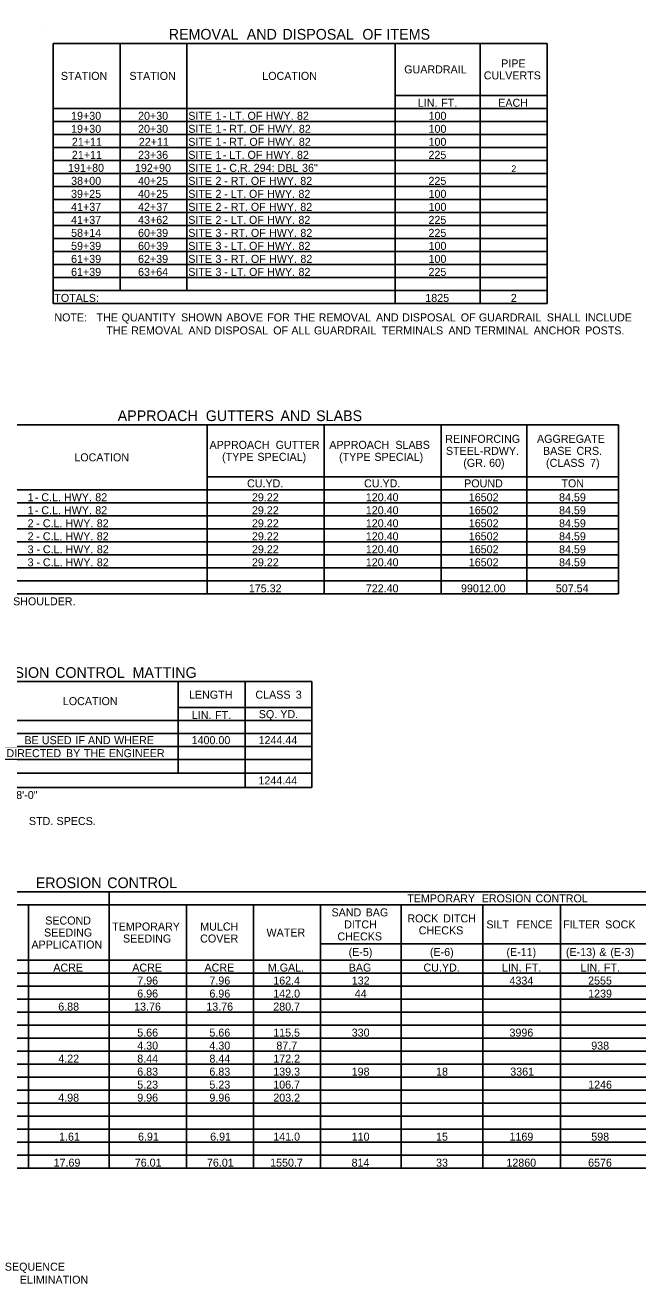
# Model space of a CAD drawing. Extents: x 977434 to 989596, y 1525697 to 1528336.
# Drawn here: x 981393 to 981852, y 1527392 to 1528336 of the extents above; entities that cross this region are included whole.
import ezdxf

# ---------------------------------------------------------------- set-up
doc = ezdxf.new("R2010")
doc.units = 0
doc.layers.add('Default', color=7, linetype='Continuous')
doc.layers.add('R_Border Prem', color=7, linetype='Continuous')

msp = doc.modelspace()

# ---------------------------------------------------------------- linework, layer by layer
at = {"layer": 'Default'}
for p, q in [((981413.79, 1528322.03), (981784.29, 1528322.03)), ((981413.79, 1528127.03), (981413.79, 1528322.03)), ((981413.79, 1528127.03), (981413.79, 1528322.03)), ((981464, 1528136.78), (981464, 1528322.03)), ((981514.21, 1528136.78), (981514.21, 1528322.03)), ((981670.21, 1528127.03), (981670.21, 1528322.03)), ((981734.08, 1528127.03), (981734.08, 1528322.03)), ((981784.29, 1528127.03), (981784.29, 1528322.03)), ((981784.29, 1528127.03), (981784.29, 1528322.03)), ((981670.21, 1528283.03), (981784.29, 1528283.03)), ((981413.79, 1528273.28), (981784.29, 1528273.28)), ((981464, 1528136.78), (981464, 1528273.28)), ((981514.21, 1528136.78), (981514.21, 1528273.28)), ((981413.79, 1528263.53), (981784.29, 1528263.53)), ((981413.79, 1528253.78), (981784.29, 1528253.78)), ((981413.79, 1528244.03), (981784.29, 1528244.03)), ((981413.79, 1528234.28), (981784.29, 1528234.28)), ((981413.79, 1528224.53), (981784.29, 1528224.53)), ((981413.79, 1528214.78), (981784.29, 1528214.78)), ((981413.79, 1528205.03), (981784.29, 1528205.03)), ((981413.79, 1528195.28), (981784.29, 1528195.28)), ((981413.79, 1528185.53), (981784.29, 1528185.53)), ((981413.79, 1528175.78), (981784.29, 1528175.78)), ((981413.79, 1528166.03), (981784.29, 1528166.03)), ((981413.79, 1528156.28), (981784.29, 1528156.28)), ((981413.79, 1528146.53), (981784.29, 1528146.53)), ((981670.21, 1528127.03), (981670.21, 1528146.53)), ((981413.79, 1528136.78), (981784.29, 1528136.78)), ((981670.21, 1528136.78), (981734.08, 1528136.78)), ((981734.08, 1528136.78), (981784.29, 1528136.78)), ((981413.79, 1528127.03), (981784.29, 1528127.03)), ((981272.88, 1528036.08), (981837.89, 1528036.08)), ((981529.31, 1527909.33), (981529.31, 1528036.08)), ((981617.06, 1527909.33), (981617.06, 1528036.08)), ((981704.81, 1527909.33), (981704.81, 1528036.08)), ((981769.16, 1527909.33), (981769.16, 1528036.08)), ((981837.89, 1527909.33), (981837.89, 1528036.08)), ((981529.31, 1527997.08), (981837.89, 1527997.08)), ((981617.06, 1527909.33), (981617.06, 1527997.08)), ((981704.81, 1527909.33), (981704.81, 1527997.08)), ((981769.16, 1527909.33), (981769.16, 1527997.08)), ((981837.89, 1527909.33), (981837.89, 1527997.08)), ((981272.88, 1527987.33), (981837.89, 1527987.33)), ((981529.31, 1527909.33), (981529.31, 1527987.33)), ((981272.88, 1527977.58), (981837.89, 1527977.58)), ((981272.88, 1527967.83), (981837.89, 1527967.83)), ((981272.88, 1527958.08), (981837.89, 1527958.08)), ((981272.88, 1527948.33), (981837.89, 1527948.33)), ((981272.88, 1527938.58), (981837.89, 1527938.58)), ((981272.88, 1527928.83), (981837.89, 1527928.83)), ((981272.88, 1527919.08), (981837.89, 1527919.08)), ((981272.88, 1527909.33), (981837.89, 1527909.33)), ((981277.44, 1527843.57), (981607.96, 1527843.57)), ((981507.54, 1527774.83), (981507.54, 1527843.57)), ((981557.75, 1527764.11), (981557.75, 1527843.57)), ((981607.96, 1527764.11), (981607.96, 1527843.57)), ((981607.96, 1527764.11), (981607.96, 1527843.57)), ((981507.54, 1527824.07), (981607.96, 1527824.07)), ((981277.44, 1527814.32), (981607.96, 1527814.32)), ((981507.54, 1527774.83), (981507.54, 1527814.32)), ((981557.75, 1527774.83), (981557.75, 1527814.32)), ((981277.44, 1527804.57), (981607.96, 1527804.57)), ((981277.44, 1527794.82), (981607.96, 1527794.82)), ((981277.44, 1527785.07), (981607.96, 1527785.07)), ((981277.44, 1527774.83), (981607.96, 1527774.83)), ((981377.86, 1527774.83), (981507.54, 1527774.83)), ((981557.75, 1527774.83), (981607.96, 1527774.83)), ((981277.44, 1527764.11), (981607.96, 1527764.11)), ((980869.9, 1527685.95), (982040.39, 1527685.95)), ((981455.87, 1527676.2), (981455.87, 1527685.95)), ((981455.87, 1527478.77), (981455.87, 1527685.95)), ((981194.57, 1527676.2), (982040.39, 1527676.2)), ((981395.42, 1527478.77), (981395.42, 1527676.2)), ((981513.89, 1527478.77), (981513.89, 1527676.2)), ((981564.1, 1527478.77), (981564.1, 1527676.2)), ((981614.31, 1527478.77), (981614.31, 1527676.2)), ((981674.76, 1527478.77), (981674.76, 1527676.2)), ((981736.19, 1527478.77), (981736.19, 1527676.2)), ((981794.2, 1527478.77), (981794.2, 1527676.2)), ((981614.31, 1527646.95), (981914.12, 1527646.95)), ((981794.2, 1527646.95), (981914.12, 1527646.95)), ((981194.57, 1527634.77), (982040.39, 1527634.77)), ((981395.42, 1527488.52), (981395.42, 1527634.77)), ((981455.87, 1527488.52), (981455.87, 1527634.77)), ((981513.89, 1527478.77), (981513.89, 1527634.77)), ((981564.1, 1527478.77), (981564.1, 1527634.77)), ((981614.31, 1527488.52), (981614.31, 1527634.77)), ((981674.76, 1527488.52), (981674.76, 1527634.77)), ((981736.19, 1527488.52), (981736.19, 1527634.77)), ((981794.2, 1527478.77), (981794.2, 1527634.77)), ((980869.9, 1527625.02), (982040.39, 1527625.02)), ((980869.9, 1527615.27), (982040.39, 1527615.27)), ((980869.9, 1527605.52), (982040.39, 1527605.52)), ((980869.9, 1527595.77), (982040.39, 1527595.77)), ((980869.9, 1527586.02), (982040.39, 1527586.02)), ((980869.9, 1527576.27), (982040.39, 1527576.27)), ((980869.9, 1527566.52), (982040.39, 1527566.52)), ((980869.9, 1527556.77), (982040.39, 1527556.77)), ((980869.9, 1527547.02), (982040.39, 1527547.02)), ((980869.9, 1527537.27), (982040.39, 1527537.27)), ((980869.9, 1527527.52), (982040.39, 1527527.52)), ((980869.9, 1527517.77), (982040.39, 1527517.77)), ((980869.9, 1527508.02), (982040.39, 1527508.02)), ((980869.9, 1527498.27), (982040.39, 1527498.27)), ((980869.9, 1527488.52), (981914.12, 1527488.52)), ((981244.79, 1527488.52), (981455.87, 1527488.52)), ((981455.87, 1527488.52), (981513.89, 1527488.52)), ((981513.89, 1527488.52), (981736.19, 1527488.52)), ((981736.19, 1527488.52), (981914.12, 1527488.52)), ((980869.9, 1527478.77), (982040.39, 1527478.77))]:
    msp.add_line(p, q, dxfattribs=at)
at = {"layer": 'R_Border Prem'}
msp.add_line((981407.94, 1528335.68), (981407.94, 1528335.68), dxfattribs=at)

# ---------------------------------------------------------------- texts
at = {"layer": 'Default'}
for s, height, p in [('REMOVAL', 8, (981500.51, 1528324.86)), (' AND', 8, (981556.07, 1528324.86)), (' DISPOSAL', 8, (981582.84, 1528324.86)), (' OF', 8, (981642.75, 1528324.86)), (' ITEMS', 8, (981660.86, 1528324.86)), ('PIPE', 6, (981749.84, 1528304.03)), ('STATION', 6, (981419.67, 1528294.66)), ('STATION', 6, (981471.05, 1528294.66)), ('LOCATION', 6, (981570.66, 1528294.66)), ('GUARDRAIL', 6, (981677.12, 1528299.53)), ('CULVERTS', 6, (981736.8, 1528295.03)), ('LIN.', 6, (981687.36, 1528274.48)), (' FT.', 6, (981702.61, 1528274.48)), ('EACH', 6, (981747.63, 1528274.48)), ('19+30', 6, (981427.33, 1528264.73)), ('20+30', 6, (981477.54, 1528264.73)), ('SITE', 6, (981515.19, 1528264.73)), (' 1', 6, (981533.38, 1528264.73)), (' LT.', 6, (981543.68, 1528264.73)), (' OF', 6, (981557.39, 1528264.73)), (' HWY.', 6, (981570.97, 1528264.73)), (' 82', 6, (981594.46, 1528264.73)), ('100', 6, (981695.36, 1528264.73)), (' -', 6, (981538.82, 1528264.73)), ('19+30', 6, (981427.33, 1528254.98)), ('20+30', 6, (981477.54, 1528254.98)), ('SITE', 6, (981515.19, 1528254.98)), (' 1', 6, (981533.38, 1528254.98)), (' -', 6, (981538.82, 1528254.98)), (' RT.', 6, (981543.68, 1528254.98)), (' OF', 6, (981558.78, 1528254.98)), (' HWY.', 6, (981572.37, 1528254.98)), (' 82', 6, (981595.85, 1528254.98)), ('100', 6, (981695.36, 1528254.98)), ('21+11', 6, (981427.9, 1528245.23)), ('22+11', 6, (981478.11, 1528245.23)), ('SITE', 6, (981515.19, 1528245.23)), (' 1', 6, (981533.38, 1528245.23)), (' -', 6, (981538.82, 1528245.23)), (' RT.', 6, (981543.68, 1528245.23)), (' OF', 6, (981558.78, 1528245.23)), (' HWY.', 6, (981572.37, 1528245.23)), (' 82', 6, (981595.85, 1528245.23)), ('100', 6, (981695.36, 1528245.23)), ('21+11', 6, (981427.9, 1528235.48)), ('23+36', 6, (981477.53, 1528235.48)), ('SITE', 6, (981515.19, 1528235.48)), (' 1', 6, (981533.38, 1528235.48)), (' -', 6, (981538.82, 1528235.48)), (' LT.', 6, (981543.68, 1528235.48)), (' OF', 6, (981557.39, 1528235.48)), (' HWY.', 6, (981570.97, 1528235.48)), (' 82', 6, (981594.46, 1528235.48)), ('225', 6, (981695.32, 1528235.48)), ('191+80', 6, (981425, 1528225.73)), ('192+90', 6, (981475.21, 1528225.73)), ('SITE', 6, (981515.19, 1528225.73)), (' 1', 6, (981533.38, 1528225.73)), (' -', 6, (981538.82, 1528225.73)), (' C.R.', 6, (981543.68, 1528225.73)), (' 294:', 6, (981562.04, 1528225.73)), (' DBL', 6, (981579.95, 1528225.73)), (' 36"', 6, (981598.28, 1528225.73)), ('2', 5, (981757.43, 1528225.53)), ('38+00', 6, (981427.33, 1528215.98)), ('40+25', 6, (981477.51, 1528215.98)), ('SITE', 6, (981515.19, 1528215.98)), (' 2', 6, (981533.38, 1528215.98)), (' -', 6, (981539.92, 1528215.98)), (' RT.', 6, (981544.78, 1528215.98)), (' OF', 6, (981559.88, 1528215.98)), (' HWY.', 6, (981573.47, 1528215.98)), (' 82', 6, (981596.95, 1528215.98)), ('225', 6, (981695.32, 1528215.98)), ('39+25', 6, (981427.3, 1528206.23)), ('40+25', 6, (981477.51, 1528206.23)), ('SITE', 6, (981515.19, 1528206.23)), (' 2', 6, (981533.38, 1528206.23)), (' -', 6, (981539.92, 1528206.23)), (' LT.', 6, (981544.78, 1528206.23)), (' OF', 6, (981558.48, 1528206.23)), (' HWY.', 6, (981572.07, 1528206.23)), (' 82', 6, (981595.55, 1528206.23)), ('100', 6, (981695.36, 1528206.23)), ('41+37', 6, (981427.32, 1528196.48)), ('42+37', 6, (981477.53, 1528196.48)), ('SITE', 6, (981515.19, 1528196.48)), (' 2', 6, (981533.38, 1528196.48)), (' -', 6, (981539.92, 1528196.48)), (' RT.', 6, (981544.78, 1528196.48)), (' OF', 6, (981559.88, 1528196.48)), (' HWY.', 6, (981573.47, 1528196.48)), (' 82', 6, (981596.95, 1528196.48)), ('100', 6, (981695.36, 1528196.48)), ('41+37', 6, (981427.32, 1528186.73)), ('43+62', 6, (981477.56, 1528186.73)), ('SITE', 6, (981515.19, 1528186.73)), (' 2', 6, (981533.38, 1528186.73)), (' -', 6, (981539.92, 1528186.73)), (' LT.', 6, (981544.78, 1528186.73)), (' OF', 6, (981558.48, 1528186.73)), (' HWY.', 6, (981572.07, 1528186.73)), (' 82', 6, (981595.55, 1528186.73)), ('225', 6, (981695.32, 1528186.73)), ('58+14', 6, (981427.33, 1528176.98)), ('60+39', 6, (981477.53, 1528176.98)), ('SITE', 6, (981515.19, 1528176.98)), (' 3', 6, (981533.38, 1528176.98)), (' -', 6, (981539.99, 1528176.98)), (' RT.', 6, (981544.84, 1528176.98)), (' OF', 6, (981559.94, 1528176.98)), (' HWY.', 6, (981573.53, 1528176.98)), (' 82', 6, (981597.01, 1528176.98)), ('225', 6, (981695.32, 1528176.98)), ('59+39', 6, (981427.31, 1528167.23)), ('60+39', 6, (981477.53, 1528167.23)), ('SITE', 6, (981515.19, 1528167.23)), (' 3', 6, (981533.38, 1528167.23)), (' -', 6, (981539.99, 1528167.23)), (' LT.', 6, (981544.84, 1528167.23)), (' OF', 6, (981558.55, 1528167.23)), (' HWY.', 6, (981572.13, 1528167.23)), (' 82', 6, (981595.62, 1528167.23)), ('100', 6, (981695.36, 1528167.23)), ('61+39', 6, (981427.31, 1528157.48)), ('62+39', 6, (981477.53, 1528157.48)), ('SITE', 6, (981515.19, 1528157.48)), (' 3', 6, (981533.38, 1528157.48)), (' -', 6, (981539.99, 1528157.48)), (' RT.', 6, (981544.84, 1528157.48)), (' OF', 6, (981559.94, 1528157.48)), (' HWY.', 6, (981573.53, 1528157.48)), (' 82', 6, (981597.01, 1528157.48)), ('100', 6, (981695.36, 1528157.48)), ('61+39', 6, (981427.31, 1528147.73)), ('63+64', 6, (981477.55, 1528147.73)), ('SITE', 6, (981515.19, 1528147.73)), (' 3', 6, (981533.38, 1528147.73)), (' -', 6, (981539.99, 1528147.73)), (' LT.', 6, (981544.84, 1528147.73)), (' OF', 6, (981558.55, 1528147.73)), (' HWY.', 6, (981572.13, 1528147.73)), (' 82', 6, (981595.62, 1528147.73)), ('225', 6, (981695.32, 1528147.73)), ('TOTALS:', 6, (981414.76, 1528128.23)), ('1825', 6, (981692.95, 1528128.23)), ('2', 6, (981757.06, 1528128.23)), ('NOTE:', 6, (981414.76, 1528113.61)), (' QUANTITY', 6, (981462.96, 1528113.61)), (' SHOWN', 6, (981507.61, 1528113.61)), (' ABOVE', 6, (981541.39, 1528113.61)), (' FOR', 6, (981572.16, 1528113.61)), (' REMOVAL', 6, (981610.72, 1528113.61)), (' DISPOSAL', 6, (981673.33, 1528113.61)), (' OF', 6, (981717.3, 1528113.61)), (' GUARDRAIL', 6, (981730.89, 1528113.61)), (' SHALL', 6, (981781.83, 1528113.61)), (' INCLUDE', 6, (981810.42, 1528113.61)), ('   THE', 6, (981439.65, 1528113.61)), (' THE', 6, (981592.07, 1528113.61)), (' AND', 6, (981653.75, 1528113.61)), ('THE', 6, (981453.76, 1528103.86)), (' REMOVAL', 6, (981470.09, 1528103.86)), (' AND', 6, (981513.12, 1528103.86)), (' DISPOSAL', 6, (981532.7, 1528103.86)), (' OF', 6, (981576.66, 1528103.86)), (' ALL', 6, (981590.25, 1528103.86)), (' GUARDRAIL', 6, (981607.19, 1528103.86)), (' TERMINALS', 6, (981658.14, 1528103.86)), (' AND', 6, (981708.01, 1528103.86)), (' TERMINAL', 6, (981727.59, 1528103.86)), (' ANCHOR', 6, (981772.01, 1528103.86)), (' POSTS.', 6, (981810.56, 1528103.86)), ('APPROACH', 8, (981462.24, 1528038.9)), (' GUTTERS', 8, (981525.35, 1528038.9)), (' AND', 8, (981581.32, 1528038.9)), (' SLABS', 8, (981608.09, 1528038.9)), ('REINFORCING', 6, (981707.89, 1528022.58)), ('AGGREGATE', 6, (981776.72, 1528022.58)), ('APPROACH', 6, (981531.14, 1528018.08)), (' GUTTER', 6, (981578.47, 1528018.08)), ('APPROACH', 6, (981620.93, 1528018.08)), (' SLABS', 6, (981668.27, 1528018.08)), ('STEEL-RDWY.', 6, (981708.39, 1528013.58)), ('BASE', 6, (981781.19, 1528013.58)), (' CRS.', 6, (981804.07, 1528013.58)), ('LOCATION', 6, (981429.75, 1528008.7)), ('(TYPE', 6, (981540.53, 1528009.08)), (' SPECIAL)', 6, (981564.81, 1528009.08)), ('(TYPE', 6, (981628.28, 1528009.08)), (' SPECIAL)', 6, (981652.56, 1528009.08)), ('(GR.', 6, (981721.42, 1528004.58)), (' 60)', 6, (981738.54, 1528004.58)), ('(CLASS', 6, (981783.46, 1528004.58)), (' 7)', 6, (981814.25, 1528004.58)), ('CU.YD.', 6, (981559.26, 1527989.2)), ('CU.YD.', 6, (981647.01, 1527989.2)), ('POUND', 6, (981722.05, 1527989.2)), ('TON', 6, (981795.01, 1527989.2)), (' 1', 6, (981392.47, 1527978.78)), (' -', 6, (981397.92, 1527978.78)), (' C.L.', 6, (981402.77, 1527978.78)), (' HWY.', 6, (981419.74, 1527978.78)), (' 82', 6, (981443.22, 1527978.78)), ('29.22', 6, (981562.92, 1527978.78)), ('120.40', 6, (981648.32, 1527978.78)), ('16502', 6, (981725.55, 1527978.78)), ('84.59', 6, (981793.23, 1527978.78)), (' 1', 6, (981392.47, 1527969.03)), (' -', 6, (981397.92, 1527969.03)), (' C.L.', 6, (981402.77, 1527969.03)), (' HWY.', 6, (981419.74, 1527969.03)), (' 82', 6, (981443.22, 1527969.03)), ('29.22', 6, (981562.92, 1527969.03)), ('120.40', 6, (981648.32, 1527969.03)), ('16502', 6, (981725.55, 1527969.03)), ('84.59', 6, (981793.23, 1527969.03)), (' 2', 6, (981392.47, 1527959.28)), (' -', 6, (981399.01, 1527959.28)), (' C.L.', 6, (981403.87, 1527959.28)), (' HWY.', 6, (981420.84, 1527959.28)), (' 82', 6, (981444.32, 1527959.28)), ('29.22', 6, (981562.92, 1527959.28)), ('120.40', 6, (981648.32, 1527959.28)), ('16502', 6, (981725.55, 1527959.28)), ('84.59', 6, (981793.23, 1527959.28)), (' 2', 6, (981392.47, 1527949.53)), (' -', 6, (981399.01, 1527949.53)), (' C.L.', 6, (981403.87, 1527949.53)), (' HWY.', 6, (981420.84, 1527949.53)), (' 82', 6, (981444.32, 1527949.53)), ('29.22', 6, (981562.92, 1527949.53)), ('120.40', 6, (981648.32, 1527949.53)), ('16502', 6, (981725.55, 1527949.53)), ('84.59', 6, (981793.23, 1527949.53)), (' 3', 6, (981392.47, 1527939.78)), (' -', 6, (981399.08, 1527939.78)), (' C.L.', 6, (981403.93, 1527939.78)), (' HWY.', 6, (981420.9, 1527939.78)), (' 82', 6, (981444.38, 1527939.78)), ('29.22', 6, (981562.92, 1527939.78)), ('120.40', 6, (981648.32, 1527939.78)), ('16502', 6, (981725.55, 1527939.78)), ('84.59', 6, (981793.23, 1527939.78)), (' 3', 6, (981392.47, 1527930.03)), (' -', 6, (981399.08, 1527930.03)), (' C.L.', 6, (981403.93, 1527930.03)), (' HWY.', 6, (981420.9, 1527930.03)), (' 82', 6, (981444.38, 1527930.03)), ('29.22', 6, (981562.92, 1527930.03)), ('120.40', 6, (981648.32, 1527930.03)), ('16502', 6, (981725.55, 1527930.03)), ('84.59', 6, (981793.23, 1527930.03)), ('175.32', 6, (981560.58, 1527910.53)), ('722.40', 6, (981648.32, 1527910.53)), ('99012.00', 6, (981719.71, 1527910.53)), ('507.54', 6, (981790.81, 1527910.53)), ('  SHOULDER.', 6, (981379.36, 1527900.78)), ('EROSION', 8, (981361.68, 1527846.4)), (' CONTROL', 8, (981412.34, 1527846.4)), (' MATTING', 8, (981470.38, 1527846.4)), ('LENGTH', 6, (981515.73, 1527830.82)), ('CLASS', 6, (981565.54, 1527830.82)), (' 3', 6, (981593.55, 1527830.82)), ('LOCATION', 6, (981421.15, 1527825.95)), ('LIN.', 6, (981517.86, 1527815.52)), (' FT.', 6, (981533.11, 1527815.52)), ('SQ.', 6, (981568.06, 1527816.2)), (' YD.', 6, (981581.93, 1527816.2)), (' BE', 6, (981390.11, 1527796.7)), (' USED', 6, (981403.17, 1527796.7)), (' IF', 6, (981428.35, 1527796.7)), (' AND', 6, (981437.74, 1527796.7)), (' WHERE', 6, (981457.32, 1527796.7)), ('1400.00', 6, (981517.7, 1527796.7)), ('1244.44', 6, (981567.92, 1527796.7)), ('DIRECTED', 6, (981378.84, 1527786.95)), (' BY', 6, (981421.25, 1527786.95)), (' THE', 6, (981434.7, 1527786.95)), (' ENGINEER', 6, (981453.34, 1527786.95)), ('1244.44', 6, (981567.81, 1527766.47)), (' 8\'-0"', 6, (981383.93, 1527755.56)), (' STD.', 6, (981393.47, 1527736.06)), (' SPECS.', 6, (981414.16, 1527736.06)), ('EROSION', 8, (981400.8, 1527688.78)), (' CONTROL', 8, (981451.45, 1527688.78)), ('TEMPORARY', 6, (981679.41, 1527678.08)), (' EROSION', 6, (981733, 1527678.08)), (' CONTROL', 6, (981773.32, 1527678.08)), ('SECOND', 6, (981407.92, 1527661.49)), ('SAND', 6, (981622.64, 1527667.58)), (' BAG', 6, (981645.98, 1527667.58)), ('ROCK', 6, (981679.49, 1527663.08)), (' DITCH', 6, (981704.16, 1527663.08)), ('SEEDING', 6, (981407.03, 1527652.49)), ('TEMPORARY', 6, (981458.09, 1527656.99)), ('MULCH', 6, (981524.18, 1527656.99)), ('WATER', 6, (981573.86, 1527652.49)), ('DITCH', 6, (981632.05, 1527658.58)), ('CHECKS', 6, (981687.98, 1527654.08)), ('SILT', 6, (981738.71, 1527658.58)), ('  FENCE', 6, (981756.7, 1527658.58)), ('FILTER', 6, (981796.26, 1527658.58)), (' SOCK', 6, (981825.56, 1527658.58)), ('APPLICATION', 6, (981397.57, 1527643.49)), ('SEEDING', 6, (981466.27, 1527647.99)), ('COVER', 6, (981524.11, 1527647.99)), ('CHECKS', 6, (981627.04, 1527649.58)), ('(E-5)', 6, (981635.44, 1527637.86)), ('(E-6)', 6, (981696.38, 1527637.86)), ('(E-11)', 6, (981753.77, 1527637.86)), ('(E-13)', 6, (981798.38, 1527637.86)), (' &', 6, (981821.22, 1527637.86)), (' (E-3)', 6, (981829.47, 1527637.86)), ('ACRE', 6, (981413.98, 1527626.22)), ('ACRE', 6, (981473.21, 1527626.22)), ('ACRE', 6, (981527.32, 1527626.22)), ('M.GAL.', 6, (981574.83, 1527626.22)), ('BAG', 6, (981635.48, 1527626.22)), ('CU.YD.', 6, (981691.56, 1527626.22)), ('LIN.', 6, (981750.4, 1527626.22)), (' FT.', 6, (981765.66, 1527626.22)), ('LIN.', 6, (981809.39, 1527626.22)), (' FT.', 6, (981824.65, 1527626.22)), ('7.96', 6, (981476.92, 1527616.47)), ('7.96', 6, (981531.03, 1527616.47)), ('162.4', 6, (981578.93, 1527616.47)), ('132', 6, (981637.77, 1527616.47)), ('4334', 6, (981756.08, 1527616.47)), ('2555', 6, (981815.03, 1527616.47)), ('6.96', 6, (981476.92, 1527606.72)), ('6.96', 6, (981531.03, 1527606.72)), ('142.0', 6, (981578.92, 1527606.72)), ('44', 6, (981640.08, 1527606.72)), ('1239', 6, (981815.05, 1527606.72)), ('6.88', 6, (981417.68, 1527596.97)), ('13.76', 6, (981474.59, 1527596.97)), ('13.76', 6, (981528.7, 1527596.97)), ('280.7', 6, (981578.91, 1527596.97)), ('5.66', 6, (981476.92, 1527577.47)), ('5.66', 6, (981531.03, 1527577.47)), ('115.5', 6, (981578.89, 1527577.47)), ('330', 6, (981637.75, 1527577.47)), ('3996', 6, (981756.06, 1527577.47)), ('4.30', 6, (981476.93, 1527567.72)), ('4.30', 6, (981531.04, 1527567.72)), ('87.7', 6, (981581.24, 1527567.72)), ('938', 6, (981817.38, 1527567.72)), ('4.22', 6, (981417.72, 1527557.97)), ('8.44', 6, (981476.93, 1527557.97)), ('8.44', 6, (981531.04, 1527557.97)), ('172.2', 6, (981578.94, 1527557.97)), ('6.83', 6, (981476.92, 1527548.22)), ('6.83', 6, (981531.03, 1527548.22)), ('139.3', 6, (981578.91, 1527548.22)), ('198', 6, (981637.73, 1527548.22)), ('18', 6, (981701, 1527548.22)), ('3361', 6, (981756.64, 1527548.22)), ('5.23', 6, (981476.92, 1527538.47)), ('5.23', 6, (981531.03, 1527538.47)), ('106.7', 6, (981578.91, 1527538.47)), ('1246', 6, (981815.05, 1527538.47)), ('4.98', 6, (981417.68, 1527528.72)), ('9.96', 6, (981476.92, 1527528.72)), ('9.96', 6, (981531.03, 1527528.72)), ('203.2', 6, (981578.94, 1527528.72)), ('1.61', 6, (981418.27, 1527499.47)), ('6.91', 6, (981477.5, 1527499.47)), ('6.91', 6, (981531.61, 1527499.47)), ('141.0', 6, (981578.92, 1527499.47)), ('110', 6, (981637.75, 1527499.47)), ('15', 6, (981700.98, 1527499.47)), ('1169', 6, (981756.06, 1527499.47)), ('598', 6, (981817.38, 1527499.47)), ('17.69', 6, (981414.2, 1527479.97)), ('76.01', 6, (981475.08, 1527479.97)), ('76.01', 6, (981529.19, 1527479.97)), ('1550.7', 6, (981576.58, 1527479.97)), ('814', 6, (981637.64, 1527479.97)), ('33', 6, (981701, 1527479.97)), ('12860', 6, (981753.75, 1527479.97)), ('6576', 6, (981815.01, 1527479.97)), (' SEQUENCE', 6, (981375.41, 1527401.97)), (' ELIMINATION', 6, (981386.63, 1527392.22))]:
    msp.add_text(s, height=height, dxfattribs=at).set_placement(p)

doc.saveas('drawing.dxf')
